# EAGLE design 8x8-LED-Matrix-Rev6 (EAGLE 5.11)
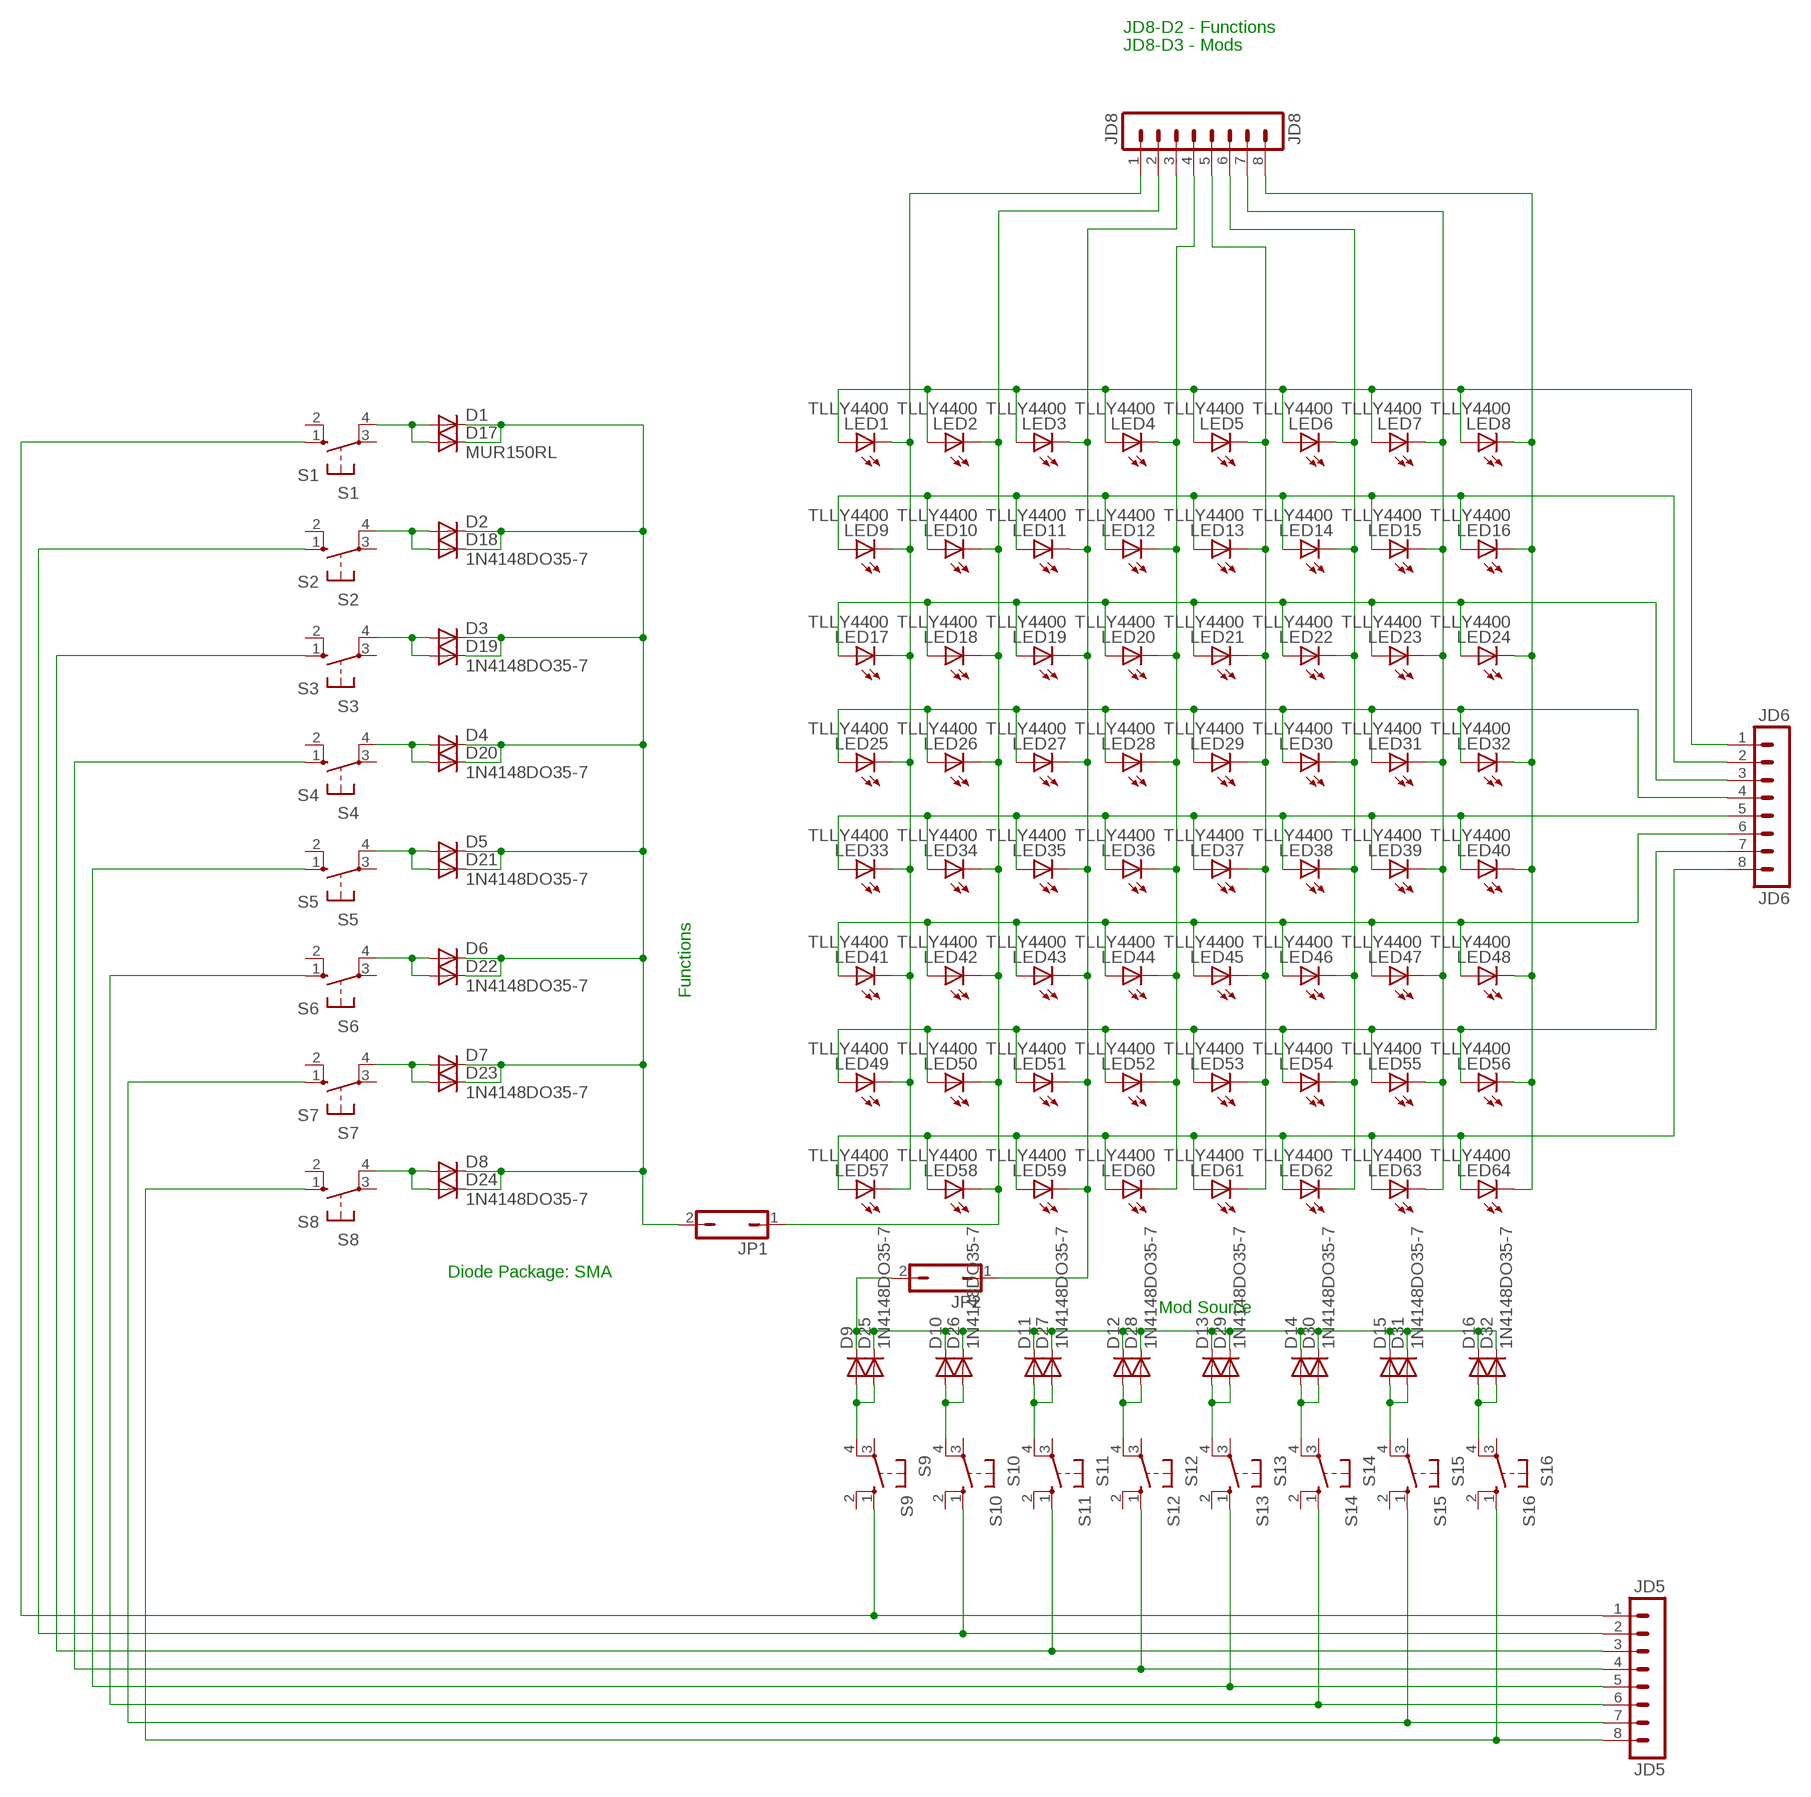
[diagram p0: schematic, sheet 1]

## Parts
D1  DIODE-DO214AC  [DO214AC]
D2  DIODE-DO214AC  [DO214AC]
D3  DIODE-DO214AC  [DO214AC]
D4  DIODE-DO214AC  [DO214AC]
D5  DIODE-DO214AC  [DO214AC]
D6  DIODE-DO214AC  [DO214AC]
D7  DIODE-DO214AC  [DO214AC]
D8  DIODE-DO214AC  [DO214AC]
D9  DIODE-DO214AC  [DO214AC]
D10  DIODE-DO214AC  [DO214AC]
D11  DIODE-DO214AC  [DO214AC]
D12  DIODE-DO214AC  [DO214AC]
D13  DIODE-DO214AC  [DO214AC]
D14  DIODE-DO214AC  [DO214AC]
D15  DIODE-DO214AC  [DO214AC]
D16  DIODE-DO214AC  [DO214AC]
D17  MUR150RL  DIODE-D-7.5  [D-7.5]
D18  1N4148DO35-7  DIODE-D-7.5  [D-7.5]
D19  1N4148DO35-7  DIODE-D-7.5  [D-7.5]
D20  1N4148DO35-7  DIODE-D-7.5  [D-7.5]
D21  1N4148DO35-7  DIODE-D-7.5  [D-7.5]
D22  1N4148DO35-7  DIODE-D-7.5  [D-7.5]
D23  1N4148DO35-7  DIODE-D-7.5  [D-7.5]
D24  1N4148DO35-7  DIODE-D-7.5  [D-7.5]
D25  1N4148DO35-7  DIODE-D-7.5  [D-7.5]
D26  1N4148DO35-7  DIODE-D-7.5  [D-7.5]
D27  1N4148DO35-7  DIODE-D-7.5  [D-7.5]
D28  1N4148DO35-7  DIODE-D-7.5  [D-7.5]
D29  1N4148DO35-7  DIODE-D-7.5  [D-7.5]
D30  1N4148DO35-7  DIODE-D-7.5  [D-7.5]
D31  1N4148DO35-7  DIODE-D-7.5  [D-7.5]
D32  1N4148DO35-7  DIODE-D-7.5  [D-7.5]
JD5  JD5  MA08-1  [MA08-1]
JD6  JD6  MA08-1  [MA08-1]
JD8  JD8  MA08-1  [MA08-1]
JP1  JP1Q  [JP1]
JP2  JP1Q  [JP1]
LED1  TLLY4400  [LED3MM]
LED2  TLLY4400  [LED3MM]
LED3  TLLY4400  [LED3MM]
LED4  TLLY4400  [LED3MM]
LED5  TLLY4400  [LED3MM]
LED6  TLLY4400  [LED3MM]
LED7  TLLY4400  [LED3MM]
LED8  TLLY4400  [LED3MM]
LED9  TLLY4400  [LED3MM]
LED10  TLLY4400  [LED3MM]
LED11  TLLY4400  [LED3MM]
LED12  TLLY4400  [LED3MM]
LED13  TLLY4400  [LED3MM]
LED14  TLLY4400  [LED3MM]
LED15  TLLY4400  [LED3MM]
LED16  TLLY4400  [LED3MM]
LED17  TLLY4400  [LED3MM]
LED18  TLLY4400  [LED3MM]
LED19  TLLY4400  [LED3MM]
LED20  TLLY4400  [LED3MM]
LED21  TLLY4400  [LED3MM]
LED22  TLLY4400  [LED3MM]
LED23  TLLY4400  [LED3MM]
LED24  TLLY4400  [LED3MM]
LED25  TLLY4400  [LED3MM]
LED26  TLLY4400  [LED3MM]
LED27  TLLY4400  [LED3MM]
LED28  TLLY4400  [LED3MM]
LED29  TLLY4400  [LED3MM]
LED30  TLLY4400  [LED3MM]
LED31  TLLY4400  [LED3MM]
LED32  TLLY4400  [LED3MM]
LED33  TLLY4400  [LED3MM]
LED34  TLLY4400  [LED3MM]
LED35  TLLY4400  [LED3MM]
LED36  TLLY4400  [LED3MM]
LED37  TLLY4400  [LED3MM]
LED38  TLLY4400  [LED3MM]
LED39  TLLY4400  [LED3MM]
LED40  TLLY4400  [LED3MM]
LED41  TLLY4400  [LED3MM]
LED42  TLLY4400  [LED3MM]
LED43  TLLY4400  [LED3MM]
LED44  TLLY4400  [LED3MM]
LED45  TLLY4400  [LED3MM]
LED46  TLLY4400  [LED3MM]
LED47  TLLY4400  [LED3MM]
LED48  TLLY4400  [LED3MM]
LED49  TLLY4400  [LED3MM]
LED50  TLLY4400  [LED3MM]
LED51  TLLY4400  [LED3MM]
LED52  TLLY4400  [LED3MM]
LED53  TLLY4400  [LED3MM]
LED54  TLLY4400  [LED3MM]
LED55  TLLY4400  [LED3MM]
LED56  TLLY4400  [LED3MM]
LED57  TLLY4400  [LED3MM]
LED58  TLLY4400  [LED3MM]
LED59  TLLY4400  [LED3MM]
LED60  TLLY4400  [LED3MM]
LED61  TLLY4400  [LED3MM]
LED62  TLLY4400  [LED3MM]
LED63  TLLY4400  [LED3MM]
LED64  TLLY4400  [LED3MM]
S1  S1  10-XX  [B3F-10XX]
S2  S2  10-XX  [B3F-10XX]
S3  S3  10-XX  [B3F-10XX]
S4  S4  10-XX  [B3F-10XX]
S5  S5  10-XX  [B3F-10XX]
S6  S6  10-XX  [B3F-10XX]
S7  S7  10-XX  [B3F-10XX]
S8  S8  10-XX  [B3F-10XX]
S9  S9  10-XX  [B3F-10XX]
S10  S10  10-XX  [B3F-10XX]
S11  S11  10-XX  [B3F-10XX]
S12  S12  10-XX  [B3F-10XX]
S13  S13  10-XX  [B3F-10XX]
S14  S14  10-XX  [B3F-10XX]
S15  S15  10-XX  [B3F-10XX]
S16  S16  10-XX  [B3F-10XX]

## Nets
N$1: JD6.1 LED1.A LED2.A LED3.A LED4.A LED5.A LED6.A LED7.A LED8.A
N$2: JD6.2 LED9.A LED10.A LED11.A LED12.A LED13.A LED14.A LED15.A LED16.A
N$3: JD6.3 LED17.A LED18.A LED19.A LED20.A LED21.A LED22.A LED23.A LED24.A
N$4: JD6.4 LED25.A LED26.A LED27.A LED28.A LED29.A LED30.A LED31.A LED32.A
N$5: JD6.5 LED33.A LED34.A LED35.A LED36.A LED37.A LED38.A LED39.A LED40.A
N$6: JD6.6 LED41.A LED42.A LED43.A LED44.A LED45.A LED46.A LED47.A LED48.A
N$7: D1.A D17.A S1.4(P1)
N$8: JD6.8 LED57.A LED58.A LED59.A LED60.A LED61.A LED62.A LED63.A LED64.A
N$9: JD8.1 LED1.K(C) LED9.K(C) LED17.K(C) LED25.K(C) LED33.K(C) LED41.K(C) LED49.K(C) LED57.K(C)
N$10: D1.C D2.C D3.C D4.C D5.C D6.C D7.C D8.C D17.C D18.C D19.C D20.C D21.C D22.C D23.C D24.C JP1.2
N$11: D2.A D18.A S2.4(P1)
N$12: JD8.4 LED4.K(C) LED12.K(C) LED20.K(C) LED28.K(C) LED36.K(C) LED44.K(C) LED52.K(C) LED60.K(C)
N$13: JD8.5 LED5.K(C) LED13.K(C) LED21.K(C) LED29.K(C) LED37.K(C) LED45.K(C) LED53.K(C) LED61.K(C)
N$14: JD8.6 LED6.K(C) LED14.K(C) LED22.K(C) LED30.K(C) LED38.K(C) LED46.K(C) LED54.K(C) LED62.K(C)
N$15: JD8.7 LED7.K(C) LED15.K(C) LED23.K(C) LED31.K(C) LED39.K(C) LED47.K(C) LED55.K(C) LED63.K(C)
N$16: JD8.8 LED8.K(C) LED16.K(C) LED24.K(C) LED32.K(C) LED40.K(C) LED48.K(C) LED56.K(C) LED64.K(C)
N$17: JD6.7 LED49.A LED50.A LED51.A LED52.A LED53.A LED54.A LED55.A LED56.A
N$18: JD5.1 S1.1(S) S9.1(S)
N$19: JD5.2 S2.1(S) S10.1(S)
N$20: JD5.4 S4.1(S) S12.1(S)
N$21: JD5.5 S5.1(S) S13.1(S)
N$22: JD5.6 S6.1(S) S14.1(S)
N$23: JD5.7 S7.1(S) S15.1(S)
N$24: JD5.8 S8.1(S) S16.1(S)
N$25: JD5.3 S3.1(S) S11.1(S)
N$26: D3.A D19.A S3.4(P1)
N$27: D4.A D20.A S4.4(P1)
N$28: D5.A D21.A S5.4(P1)
N$29: D6.A D22.A S6.4(P1)
N$30: D7.A D23.A S7.4(P1)
N$31: JD8.3 JP2.1 LED3.K(C) LED11.K(C) LED19.K(C) LED27.K(C) LED35.K(C) LED43.K(C) LED51.K(C) LED59.K(C)
N$32: D9.A D25.A S9.4(P1)
N$33: D10.A D26.A S10.4(P1)
N$34: D8.A D24.A S8.4(P1)
N$35: D11.A D27.A S11.4(P1)
N$36: D12.A D28.A S12.4(P1)
N$37: D13.A D29.A S13.4(P1)
N$38: D14.A D30.A S14.4(P1)
N$39: D15.A D31.A S15.4(P1)
N$40: D16.A D32.A S16.4(P1)
N$41: JD8.2 JP1.1 LED2.K(C) LED10.K(C) LED18.K(C) LED26.K(C) LED34.K(C) LED42.K(C) LED50.K(C) LED58.K(C)
N$42: D9.C D10.C D11.C D12.C D13.C D14.C D15.C D16.C D25.C D26.C D27.C D28.C D29.C D30.C D31.C D32.C JP2.2
Unconnected: S1.2(S1) S1.3(P) S2.2(S1) S2.3(P) S3.2(S1) S3.3(P) S4.2(S1) S4.3(P) S5.2(S1) S5.3(P) S6.2(S1) S6.3(P) S7.2(S1) S7.3(P) S8.2(S1) S8.3(P) S9.2(S1) S9.3(P) S10.2(S1) S10.3(P) S11.2(S1) S11.3(P) S12.2(S1) S12.3(P) S13.2(S1) S13.3(P) S14.2(S1) S14.3(P) S15.2(S1) S15.3(P) S16.2(S1) S16.3(P)

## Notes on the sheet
- JD8-D2 - Functions
- JD8-D3 - Mods
- Functions
- Diode Package: SMA
- Mod Source

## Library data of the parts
D1-D16 = diode:DIODE-: DIODE
D17-D32 = diodes:DIODE-: DIODE
JD5 JD6 JD8 = con-lstb:MA08-1: PIN HEADER; OC_FARNELL: unknown; OC_NEWARK: unknown
JP1 JP2 = jumper:JP1Q: JUMPER
LED1-LED64 = led:TLLY4400: Low Current (2mA) LED 3 mm Tinted Diffused Package color YELLOW; MF: VISHAY SEMICONDUCTOR; OC_FARNELL: 1612439
S1-S16 = switch-omron:10-XX: OMRON SWITCH; MPN: B3F-1000; OC_FARNELL: 176432; OC_NEWARK: 36M3542

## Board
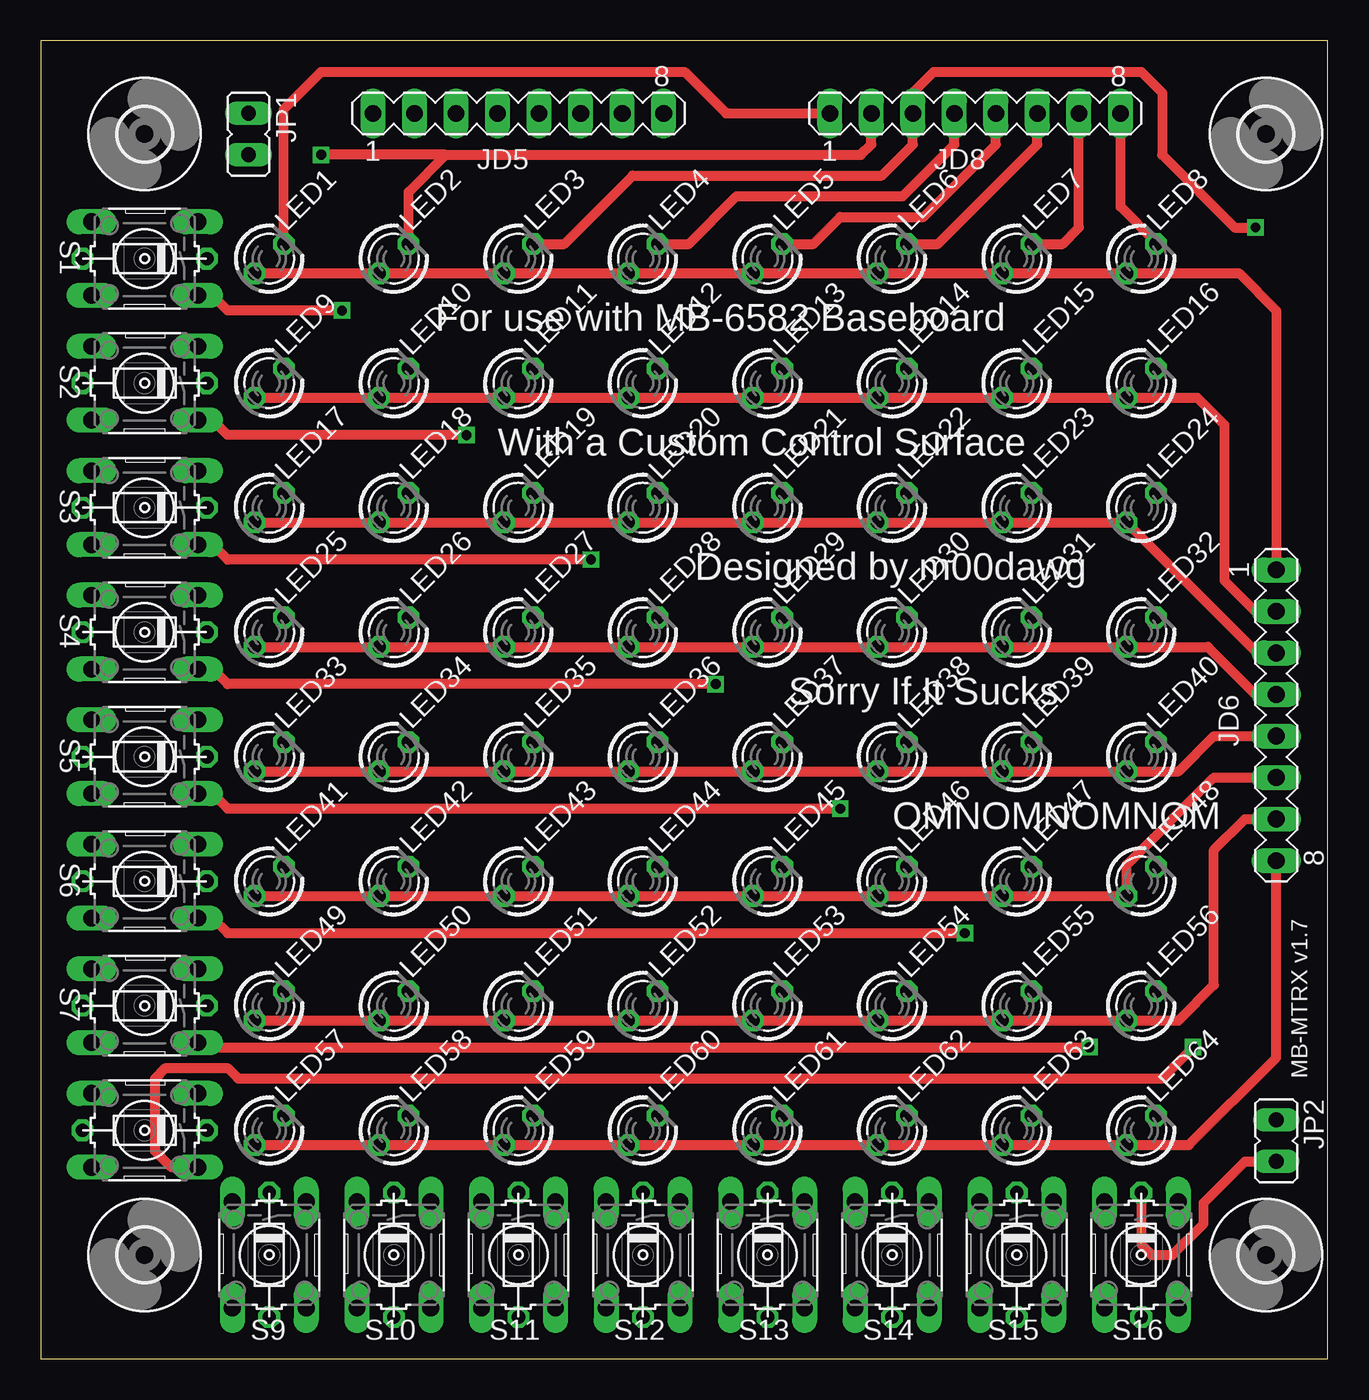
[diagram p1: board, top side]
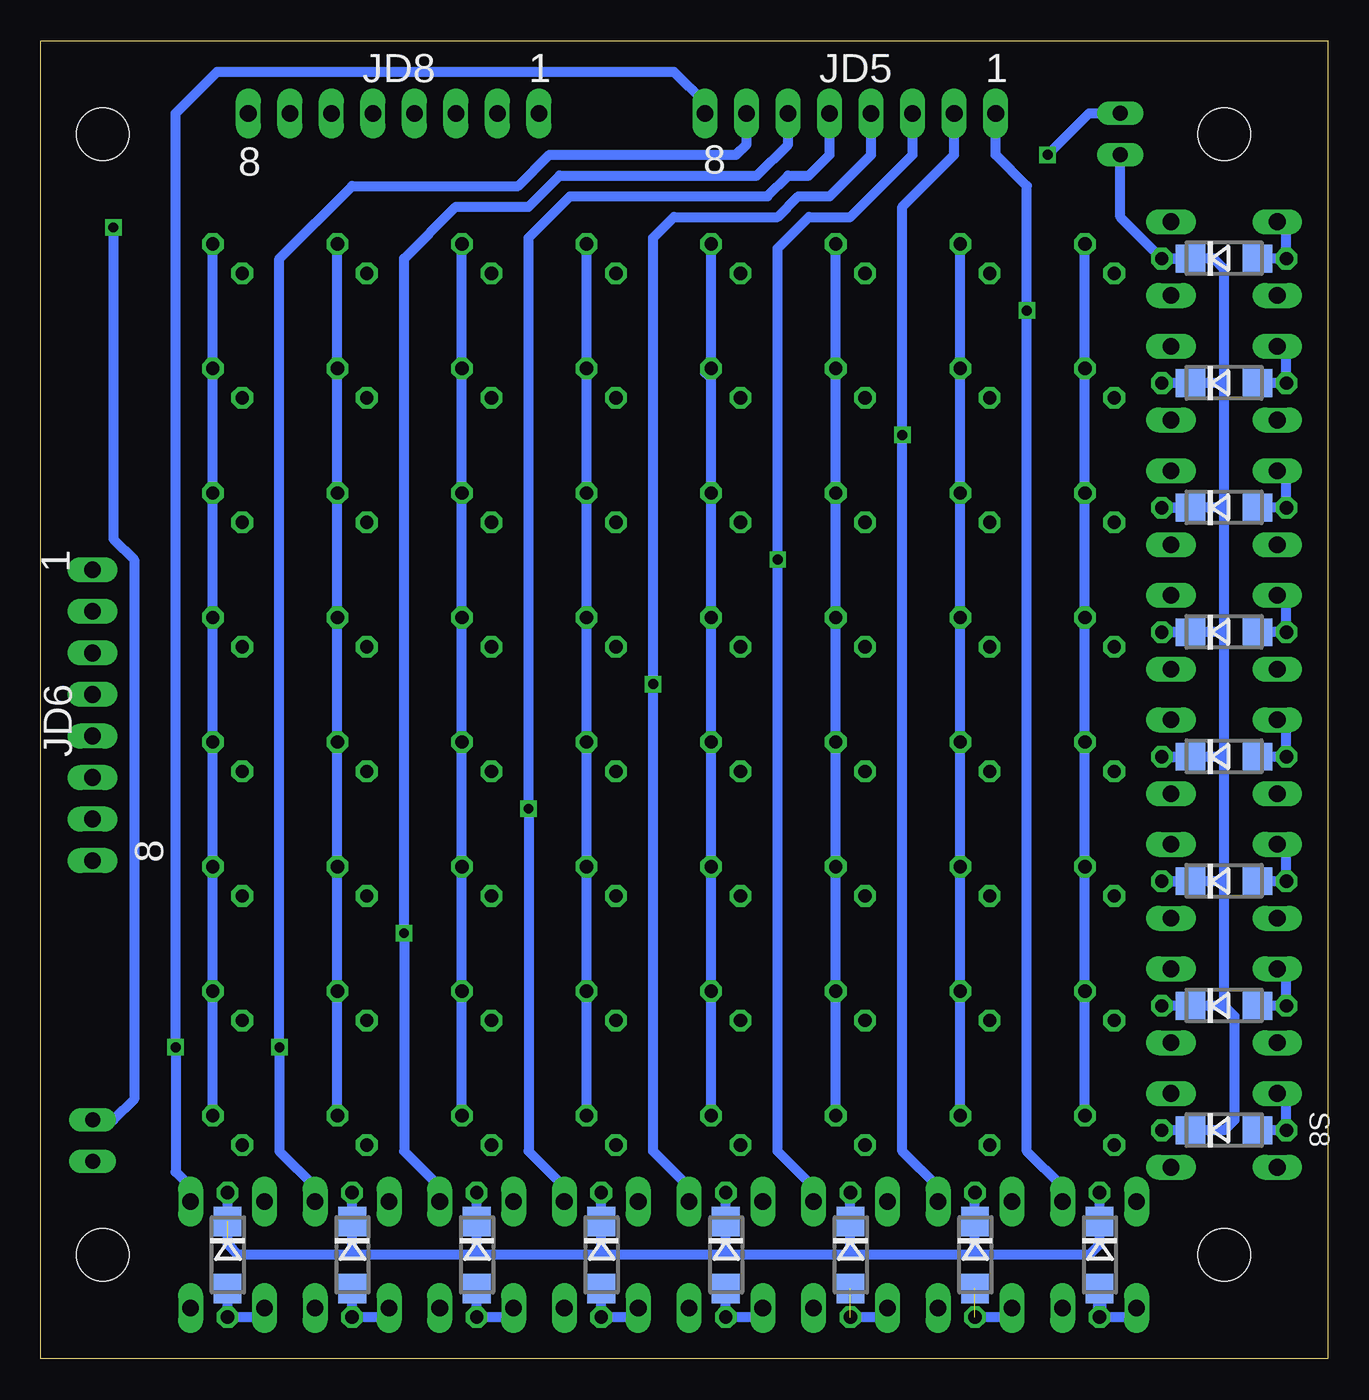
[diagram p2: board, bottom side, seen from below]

Size 78.73 x 80.64 mm. Coordinates in mm from the lower left corner, seen from the top.
Outline: 0,0 78.73,0 78.73,80.64 0,80.64 0,0
Copper layers (1*16): Top 0.035mm / dielectric 1.5mm / Bottom 0.035mm
Design rules "batchpcb": minimum track width 8mil, minimum drill 20mil, track to track 8mil, track to pad 8mil, pad to pad 8mil, via to via 8mil, smd to smd 8mil, copper to edge 40mil, drill to drill 8mil, minimum pad ring 10mil, minimum via ring 8mil, stop-mask expansion 4mil, vias tented up to drill 0mil, thermal gap 10mil

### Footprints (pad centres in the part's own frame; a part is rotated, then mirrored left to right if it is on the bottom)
DO214AC = smd 1.8 x 1.7: A 2.05,0; C -2.05,0
D-7.5 = drill 0.813 octagon: A 3.81,0; C -3.81,0
MA08-1 = drill 1.016 long: 1 -8.89,0; 2 -6.35,0; 3 -3.81,0; 4 -1.27,0; 5 1.27,0; 6 3.81,0; 7 6.35,0; 8 8.89,0
JP1 = drill 0.914 long: 1 0,-1.27; 2 0,1.27
LED3MM = drill 0.813 octagon: A -1.27,0; K 1.27,0
B3F-10XX = drill 1.016 long: 1 -3.251,2.261; 2 3.251,2.261; 3 -3.251,-2.261; 4 3.251,-2.261
3,2 = hole 3.2: 0,0

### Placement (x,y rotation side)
D1  6.35,67.31 0 bottom
D2  6.35,59.69 0 bottom
D3  6.35,52.07 0 bottom
D4  6.35,44.45 0 bottom
D5  6.35,36.83 0 bottom
D6  6.35,29.21 0 bottom
D7  6.35,21.59 0 bottom
D8  6.35,13.97 0 bottom
D9  13.97,6.35 270 bottom
D10  21.59,6.35 270 bottom
D11  29.21,6.35 270 bottom
D12  36.83,6.35 270 bottom
D13  44.45,6.35 270 bottom
D14  52.07,6.35 270 bottom
D15  59.69,6.35 270 bottom
D16  67.31,6.35 270 bottom
D17  6.35,67.31 180 top
D18  6.35,59.69 180 top
D19  6.35,52.07 180 top
D20  6.35,44.45 180 top
D21  6.35,36.83 180 top
D22  6.35,29.21 180 top
D23  6.35,21.59 180 top
D24  6.35,13.97 180 top
D25  13.97,6.35 270 top
D26  21.59,6.35 270 top
D27  29.21,6.35 270 top
D28  36.83,6.35 270 top
D29  44.45,6.35 270 top
D30  52.07,6.35 270 top
D31  59.69,6.35 270 top
D32  67.31,6.35 270 top
JD5  29.21,76.2 0 top
JD6  75.56,39.37 270 top
JD8  57.15,76.2 0 top
JP1  12.7,74.93 180 top
JP2  75.56,13.34 180 top
LED1  13.97,67.31 45 top
LED2  21.59,67.31 45 top
LED3  29.21,67.31 45 top
LED4  36.83,67.31 45 top
LED5  44.45,67.31 45 top
LED6  52.07,67.31 45 top
LED7  59.69,67.31 45 top
LED8  67.31,67.31 45 top
LED9  13.97,59.69 45 top
LED10  21.59,59.69 45 top
LED11  29.21,59.69 45 top
LED12  36.83,59.69 45 top
LED13  44.45,59.69 45 top
LED14  52.07,59.69 45 top
LED15  59.69,59.69 45 top
LED16  67.31,59.69 45 top
LED17  13.97,52.07 45 top
LED18  21.59,52.07 45 top
LED19  29.21,52.07 45 top
LED20  36.83,52.07 45 top
LED21  44.45,52.07 45 top
LED22  52.07,52.07 45 top
LED23  59.69,52.07 45 top
LED24  67.31,52.07 45 top
LED25  13.97,44.45 45 top
LED26  21.59,44.45 45 top
LED27  29.21,44.45 45 top
LED28  36.83,44.45 45 top
LED29  44.45,44.45 45 top
LED30  52.07,44.45 45 top
LED31  59.69,44.45 45 top
LED32  67.31,44.45 45 top
LED33  13.97,36.83 45 top
LED34  21.59,36.83 45 top
LED35  29.21,36.83 45 top
LED36  36.83,36.83 45 top
LED37  44.45,36.83 45 top
LED38  52.07,36.83 45 top
LED39  59.69,36.83 45 top
LED40  67.31,36.83 45 top
LED41  13.97,29.21 45 top
LED42  21.59,29.21 45 top
LED43  29.21,29.21 45 top
LED44  36.83,29.21 45 top
LED45  44.45,29.21 45 top
LED46  52.07,29.21 45 top
LED47  59.69,29.21 45 top
LED48  67.31,29.21 45 top
LED49  13.97,21.59 45 top
LED50  21.59,21.59 45 top
LED51  29.21,21.59 45 top
LED52  36.83,21.59 45 top
LED53  44.45,21.59 45 top
LED54  52.07,21.59 45 top
LED55  59.69,21.59 45 top
LED56  67.31,21.59 45 top
LED57  13.97,13.97 45 top
LED58  21.59,13.97 45 top
LED59  29.21,13.97 45 top
LED60  36.83,13.97 45 top
LED61  44.45,13.97 45 top
LED62  52.07,13.97 45 top
LED63  59.69,13.97 45 top
LED64  67.31,13.97 45 top
S1  6.35,67.31 180 top
S2  6.35,59.69 180 top
S3  6.35,52.07 180 top
S4  6.35,44.45 180 top
S5  6.35,36.83 180 top
S6  6.35,29.21 180 top
S7  6.35,21.59 180 top
S8  6.35,13.97 180 top
S9  13.97,6.35 270 top
S10  21.59,6.35 270 top
S11  29.21,6.35 270 top
S12  36.83,6.35 270 top
S13  44.45,6.35 270 top
S14  52.07,6.35 270 top
S15  59.69,6.35 270 top
S16  67.31,6.35 270 top
U$1  [3,2]  6.35,74.93 0 top
U$2  [3,2]  74.93,74.93 0 top
U$3  [3,2]  74.93,6.35 0 top
U$4  [3,2]  6.35,6.35 0 top

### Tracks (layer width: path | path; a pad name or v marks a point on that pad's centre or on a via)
N$1
  Top 0.61: JD6.1 75.56,64.14 73.29,66.41 LED8.A LED7.A LED6.A LED5.A LED4.A LED3.A LED2.A LED1.A
N$2
  Top 0.61: JD6.2 74.3,45.72 72.39,47.62 72.39,57.15 70.75,58.79 LED16.A LED15.A LED14.A LED13.A LED12.A LED11.A LED10.A LED9.A
N$3
  Top 0.61: LED17.A LED18.A LED19.A LED20.A LED21.A LED22.A LED23.A LED24.A 74.4,43.18 JD6.3
N$4
  Top 0.61: JD6.4 74.3,40.64 71.38,43.55 LED32.A LED31.A LED30.A LED29.A LED28.A LED27.A LED26.A LED25.A
N$5
  Top 0.61: JD6.5 71.75,38.1 69.59,35.93 LED40.A LED39.A LED38.A LED37.A LED36.A LED35.A LED34.A LED33.A
N$6
  Top 0.61: LED41.A LED42.A LED43.A LED44.A LED45.A LED46.A LED47.A LED48.A 66.41,30.22 71.75,35.56 JD6.6
N$7
  Bottom 0.61: D1.A D17.A 2.54,69.01 S1.4
N$8
  Top 0.61: JD6.8 75.56,18.41 70.22,13.07 LED64.A LED63.A LED62.A LED61.A LED60.A LED59.A LED58.A LED57.A
N$9
  Top 0.61: LED1.K 14.87,76.46 17.14,78.74 39.37,78.74 41.91,76.2 JD8.1
  Bottom 0.61: LED1.K LED9.K LED17.K LED25.K LED33.K LED41.K LED49.K LED57.K
N$10
  Bottom 0.61: D24.C D8.C 6.35,13.97 5.71,14.61 5.71,20.95 6.35,21.59 | D23.C D7.C 6.35,21.59 | D6.C D22.C 6.35,29.21 | D5.C D21.C 6.35,36.83 | D4.C D20.C 6.35,44.45 | D3.C D19.C 6.35,52.07 | D18.C D2.C 6.35,59.69 | D17.C D1.C | D17.C 6.99,67.31 6.35,66.67 6.35,59.69 | 6.35,21.59 6.35,29.21 | 6.35,29.21 6.35,36.83 | 6.35,36.83 6.35,44.45 | 6.35,44.45 6.35,52.07 | 6.35,52.07 6.35,59.69 | D17.C 12.7,69.85 JP1.2
N$11
  Bottom 0.61: D2.A D18.A 2.54,61.39 S2.4
N$12
  Top 0.61: JD8.4 55.88,74.3 52.7,71.12 42.55,71.12 39.63,68.21 LED4.K
  Bottom 0.61: LED4.K LED12.K 37.99,60.33 38.1,60.33 37.73,59.95 LED20.K LED28.K LED36.K LED44.K LED52.K LED60.K
N$13
  Top 0.61: JD8.5 58.42,74.3 53.98,69.85 48.9,69.85 47.25,68.21 LED5.K
  Bottom 0.61: LED5.K LED13.K LED21.K LED29.K LED37.K LED45.K LED53.K LED61.K
N$14
  Top 0.61: LED6.K 54.87,68.21 60.96,74.3 JD8.6
  Bottom 0.61: LED6.K LED14.K LED22.K LED30.K LED38.K LED46.K LED54.K LED62.K
N$15
  Top 0.61: LED7.K 62.49,68.21 63.5,69.22 JD8.7
  Bottom 0.61: LED7.K LED15.K LED23.K LED31.K LED39.K LED47.K LED55.K LED63.K
N$16
  Top 0.61: JD8.8 66.04,70.48 68.21,68.32 LED8.K
  Bottom 0.61: LED8.K LED16.K LED24.K LED32.K LED40.K LED48.K LED56.K LED64.K
N$17
  Top 0.61: JD6.7 73.66,33.02 71.75,31.11 71.75,22.86 69.59,20.69 LED56.A LED55.A LED54.A LED53.A LED52.A LED51.A LED50.A LED49.A
N$18  (via drill 0.6)
  Top 0.61: S1.1 10.52,65.05 11.43,64.14 v18.41,64.14
  Bottom 0.61: S9.1 16.23,10.52 18.41,12.7 v18.41,64.14 18.41,71.75 20.32,73.66 JD5.1
N$19  (via drill 0.6)
  Top 0.61: S2.1 10.52,57.43 11.43,56.52 v26.04,56.52
  Bottom 0.61: S10.1 23.85,10.52 26.04,12.7 v26.04,56.52 26.04,70.48 22.86,73.66 JD5.2
N$20  (via drill 0.6)
  Top 0.61: S4.1 10.52,42.19 11.43,41.27 v41.27,41.27
  Bottom 0.61: S12.1 39.09,10.52 41.27,12.7 v41.27,41.27 41.27,68.58 40.01,69.85 33.66,69.85 32.38,71.12 30.48,71.12 27.94,73.66 JD5.4
N$21  (via drill 0.6)
  Top 0.61: S5.1 10.52,34.57 11.43,33.66 v48.9,33.66
  Bottom 0.61: S13.1 46.71,10.52 48.9,12.7 v48.9,33.66 48.9,68.58 46.35,71.12 34.29,71.12 33.02,72.39 31.75,72.39 30.48,73.66 JD5.5
N$22  (via drill 0.6)
  Top 0.61: S6.1 10.52,26.95 11.43,26.04 v56.52,26.04
  Bottom 0.61: S14.1 54.33,10.52 56.52,12.7 v56.52,26.04 56.52,67.31 53.34,70.48 48.9,70.48 46.99,72.39 34.92,72.39 33.02,74.3 JD5.6
N$23  (via drill 0.6)
  Top 0.61: S7.1 10.52,19.33 10.79,19.05 v64.14,19.05
  Bottom 0.61: S15.1 61.95,10.52 64.14,12.7 v64.14,19.05 64.14,67.31 59.69,71.75 49.53,71.75 47.62,73.66 36.2,73.66 35.56,74.3 JD5.7
N$24  (via drill 0.6)
  Top 0.61: v70.48,19.05 68.58,17.14 12.06,17.14 11.43,17.78 7.62,17.78 6.99,17.14 6.99,12.7 7.98,11.71 S8.1
  Bottom 0.61: S16.1 69.57,10.52 70.48,11.43 v70.48,19.05 70.48,76.2 67.94,78.74 40.01,78.74 38.1,76.83 JD5.8
N$25  (via drill 0.6)
  Top 0.61: S3.1 10.52,49.81 11.43,48.9 v33.66,48.9
  Bottom 0.61: S11.1 31.47,10.52 33.66,12.7 v33.66,48.9 33.66,67.94 31.75,69.85 29.21,69.85 25.4,73.66 JD5.3
N$26
  Bottom 0.61: D3.A D19.A 2.54,53.77 S3.4
N$27
  Bottom 0.61: D4.A D20.A 2.54,46.15 S4.4
N$28
  Bottom 0.61: D5.A D21.A 2.54,38.53 S5.4
N$29
  Bottom 0.61: D6.A D22.A 2.54,30.91 S6.4
N$30
  Bottom 0.61: D7.A D23.A 2.54,23.29 S7.4
N$31  (via drill 0.6)
  Top 0.61: LED3.K 32.01,68.21 36.2,72.39 51.44,72.39 53.34,74.3 JD8.3 53.34,77.47 54.61,78.74 67.31,78.74 68.58,77.47 68.58,73.66 73.03,69.22 v74.3,69.22
  Bottom 0.61: LED3.K LED11.K LED19.K LED27.K LED35.K LED43.K LED51.K LED59.K | JP2.1 74.3,14.61 73.03,15.88 73.03,48.9 74.3,50.16 v74.3,69.22
N$32
  Bottom 0.61: D25.A 12.27,2.54 S9.4
  Bottom 0.813: D25.A D9.A
N$33  (1 unrouted)
  Bottom 0.61: D26.A 19.89,2.54 S10.4
N$34
  Bottom 0.61: D8.A D24.A 2.54,15.67 S8.4
N$35  (1 unrouted)
  Bottom 0.61: D27.A 27.51,2.54 S11.4
N$36
  Bottom 0.61: D12.A D28.A 35.13,2.54 S12.4
N$37
  Bottom 0.61: D13.A D29.A 42.75,2.54 S13.4
N$38
  Bottom 0.61: D14.A D30.A 50.37,2.54 S14.4
N$39
  Bottom 0.61: D15.A D31.A 57.99,2.54 S15.4
N$40
  Bottom 0.61: S16.4 65.61,2.54 D32.A D16.A
N$41  (via drill 0.6)
  Top 0.61: 24.77,73.66 v17.14,73.66 | 24.77,73.66 50.16,73.66 50.8,74.3 JD8.2 | LED2.K 22.49,71.38 24.77,73.66
  Bottom 0.61: LED2.K LED10.K LED18.K LED26.K LED34.K LED42.K LED50.K LED58.K | JP1.1 14.61,76.2 v17.14,73.66
N$42  (1 unrouted)
  Top 0.61: D32.C 67.31,6.99 67.94,6.35 69.22,6.35 71.12,8.26 71.12,9.53 73.66,12.06 JP2.2
  Bottom 0.61: D32.C 67.31,6.99 66.67,6.35 59.69,6.35 | 21.59,6.35 14.61,6.35 13.97,6.99 D9.C D25.C | 21.59,6.35 29.21,6.35 | 29.21,6.35 36.83,6.35 | 36.83,6.35 44.45,6.35 | 44.45,6.35 52.07,6.35 | 52.07,6.35 59.69,6.35 | 21.59,6.35 D10.C D26.C | 29.21,6.35 D11.C D27.C | 36.83,6.35 D12.C D28.C | 44.45,6.35 D13.C D29.C | 52.07,6.35 D14.C D30.C | 59.69,6.35 D15.C D31.C

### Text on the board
tPlace: For use with MB-6582 Baseboard | With a Custom Control Surface | Designed by m00dawg | Sorry If It Sucks | OMNOMNOMNOM | MB-MTRX v1.7
bPlace: 1 | JD5 | 1 | JD8 | 8 | 8 | 1 | JD6 | 8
